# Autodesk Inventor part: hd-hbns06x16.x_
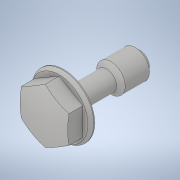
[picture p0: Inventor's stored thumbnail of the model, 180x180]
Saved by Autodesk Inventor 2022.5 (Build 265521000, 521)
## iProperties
Created: 2021-02
Part Number: hd-hbns06x16.x_
Material: 一般
Document SubType Name: Modeling
Designer: ImaoCorp
Density: 1 g/cm^3
Appearance: 既定
Sending System: SOLIDWORKS 2019-2019304
MC: AMD64
MC_MODEL: Intel64 Family 6 Model 60 Stepping 3, GenuineIntel
OS: Windows_NT
FRU: Parasolid Version 31.0, build 290,  9- 1-2019
FORMAT: text
GUISE: transmit
KEY: hd-hbns06x16
FILE: hd-hbns06x16.x_t
DATE: Mon Feb 22 15:01:02 2021
Author: ImaoCorp
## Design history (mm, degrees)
feature "Base1"
node "ソリッド1"
